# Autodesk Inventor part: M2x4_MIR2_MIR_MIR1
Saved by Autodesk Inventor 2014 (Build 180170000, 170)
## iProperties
Created: 2015-05
Part Number: M2x4_MIR2_MIR_MIR1
Material: 일반
Vendor: CBT Solutions
Document SubType Name: 모델링
Designer: Administrator
Appearance: 기본값
Company: 한국ATC센터
Author: KYOUNG IL JANG
Comments: 파생
d0: 1.000 ul
d0_1: 1.000 ul
d0_1_1: 1.000 ul
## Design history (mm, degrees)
derived "M2x4_MIR2_MIR.ipt"
feature "솔리드1::M2x4_MIR2_MIR.ipt"
tag "피쳐 태그1"
node "솔리드1"
other parameters: "d0" = 1, "d0_1" = 1, "d0_1_1" = 1
